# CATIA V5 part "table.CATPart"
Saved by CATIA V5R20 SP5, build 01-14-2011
Part number: 桌子
Material "Sunshine Orange": density 7860 kg/m3, Young's modulus 2e+11 Pa, Poisson ratio 0.266
Bounding box of the stored display mesh (mm): x -250 to 250, y -150 to 150, z -220 to 20
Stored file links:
  E:\设计\180212313林恺昇\table.CATPart
  C:\Program Files\Dassault Systemes\B20\intel_a\startup\materials\Catalog.CATMaterial
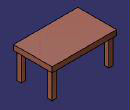
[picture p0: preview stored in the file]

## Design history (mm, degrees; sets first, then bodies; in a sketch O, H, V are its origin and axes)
Body1 (main body)
  Sketch1 on xy-plane, origin (0, 0, 0), H (1, 0, 0), V (0, 1, 0)
    line L1 (250, 150) -> (250, -150)
    line L2 (250, -150) -> (-250, -150)
    line L3 (-250, -150) -> (-250, 150)
    line L4 (-250, 150) -> (250, 150)
    length L1 = 300
    length L2 = 500
    vertical: L1 V, L3 V
    horizontal: L2 H, L4 H
    equidistance: L1 L3 O, L2 L4 O
  Pad1: profile Sketch1, direction (0, 0, -1), length 20, mirrored extent
  Sketch2 on end face of Pad1, origin (0, 0, -20), H (1, 0, 0), V (0, -1, 0)
    point P1 (220, 120)
    line L1 (237.5, 137.5) -> (237.5, 102.5)
    line L2 (237.5, 102.5) -> (202.5, 102.5)
    line L3 (202.5, 102.5) -> (202.5, 137.5)
    line L4 (202.5, 137.5) -> (237.5, 137.5)
    point P2 (237.5, 137.5)
    point P3 (237.5, 102.5)
    point P4 (202.5, 102.5)
    point P5 (202.5, 137.5)
    point P6 (-237.5, 137.5)
    point P7 (-202.5, 137.5)
    line L5 (-202.5, 137.5) -> (-237.5, 137.5)
    point P8 (-202.5, 102.5)
    line L6 (-202.5, 102.5) -> (-202.5, 137.5)
    point P9 (-237.5, 102.5)
    line L7 (-237.5, 102.5) -> (-202.5, 102.5)
    line L8 (-237.5, 137.5) -> (-237.5, 102.5)
    point P10 (-237.5, -137.5)
    point P11 (-202.5, -137.5)
    point P12 (-202.5, -102.5)
    point P13 (-237.5, -102.5)
    line L9 (-202.5, -137.5) -> (-237.5, -137.5)
    line L10 (-202.5, -102.5) -> (-202.5, -137.5)
    line L11 (-237.5, -102.5) -> (-202.5, -102.5)
    line L12 (-237.5, -137.5) -> (-237.5, -102.5)
    point P14 (220, -120)
    point P15 (237.5, -137.5)
    point P16 (237.5, -102.5)
    point P17 (202.5, -102.5)
    point P18 (202.5, -137.5)
    line L13 (237.5, -137.5) -> (237.5, -102.5)
    line L14 (237.5, -102.5) -> (202.5, -102.5)
    line L15 (202.5, -102.5) -> (202.5, -137.5)
    line L16 (202.5, -137.5) -> (237.5, -137.5)
    distance V P1 = 220
    distance H P1 = 120
    length L4 = 35
    length L1 = 35
    vertical: L1 V, L3 V
    horizontal: L2 H, L4 H
    equidistance: L1 L3 P1, L2 L4 P1
    symmetry: P2 P6 V, P5 P7 V, L4 L5 V, P4 P8 V, L3 L6 V, P3 P9 V, L2 L7 V, L1 L8 V, P6 P10 H, P7 P11 H, P8 P12 H, P9 P13 H, L5 L9 H, L6 L10 H, L7 L11 H, L8 L12 H, P1 P14 H, P2 P15 H, P3 P16 H, P4 P17 H, P5 P18 H, L1 L13 H, L2 L14 H, L3 L15 H, L4 L16 H
  Pad2: profile Sketch2, direction (0, 0, -1), length 200
  Sketch3 on end face of Pad1, origin (0, 0, -20), H (1, 0, 0), V (0, 1, 0)
    line L1 (250, 150) -> (250, -150)
    line L2 (250, -150) -> (-250, -150)
    line L3 (-250, -150) -> (-250, 150)
    line L4 (-250, 150) -> (250, 150)
    length L1 = 300
    length L2 = 500
    vertical: L1 V, L3 V
    horizontal: L2 H, L4 H
    equidistance: L1 L3 O, L2 L4 O
  Pad3: profile Sketch3, direction (0, 0, -1), length 20, mirrored extent
Current feature: Pad2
